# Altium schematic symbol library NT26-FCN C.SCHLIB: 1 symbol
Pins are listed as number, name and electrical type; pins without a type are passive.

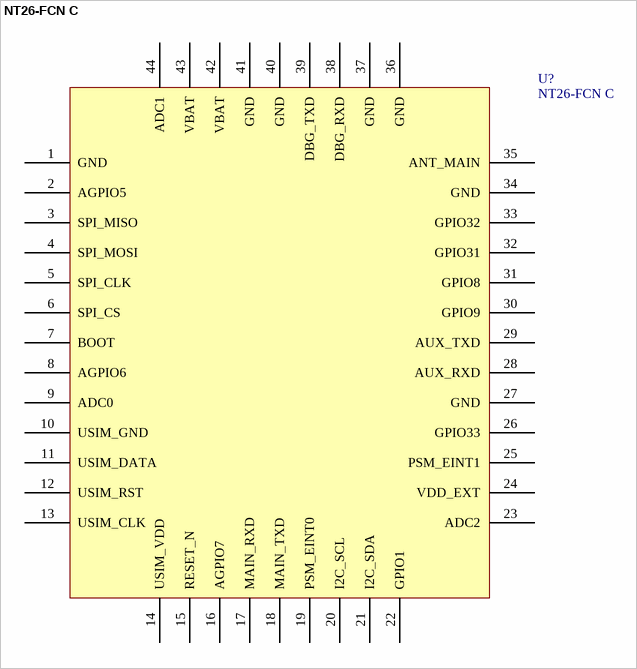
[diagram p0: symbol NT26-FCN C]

## NT26-FCN C
designator U?
footprint NT26-FCN C (Footprint not found)
pins: 1 GND, 2 AGPIO5, 3 SPI_MISO, 4 SPI_MOSI, 5 SPI_CLK, 6 SPI_CS, 7 BOOT, 8 AGPIO6, 9 ADC0, 10 USIM_GND, 11 USIM_DATA, 12 USIM_RST, 13 USIM_CLK, 14 USIM_VDD, 15 RESET_N, 16 AGPIO7, 17 MAIN_RXD, 18 MAIN_TXD, 19 PSM_EINT0, 20 I2C_SCL, 21 I2C_SDA, 22 GPIO1, 23 ADC2, 24 VDD_EXT, 25 PSM_EINT1, 26 GPIO33, 27 GND, 28 AUX_RXD, 29 AUX_TXD, 30 GPIO9, 31 GPIO8, 32 GPIO31, 33 GPIO32, 34 GND, 35 ANT_MAIN, 36 GND, 37 GND, 38 DBG_RXD, 39 DBG_TXD, 40 GND, 41 GND, 42 VBAT, 43 VBAT, 44 ADC1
